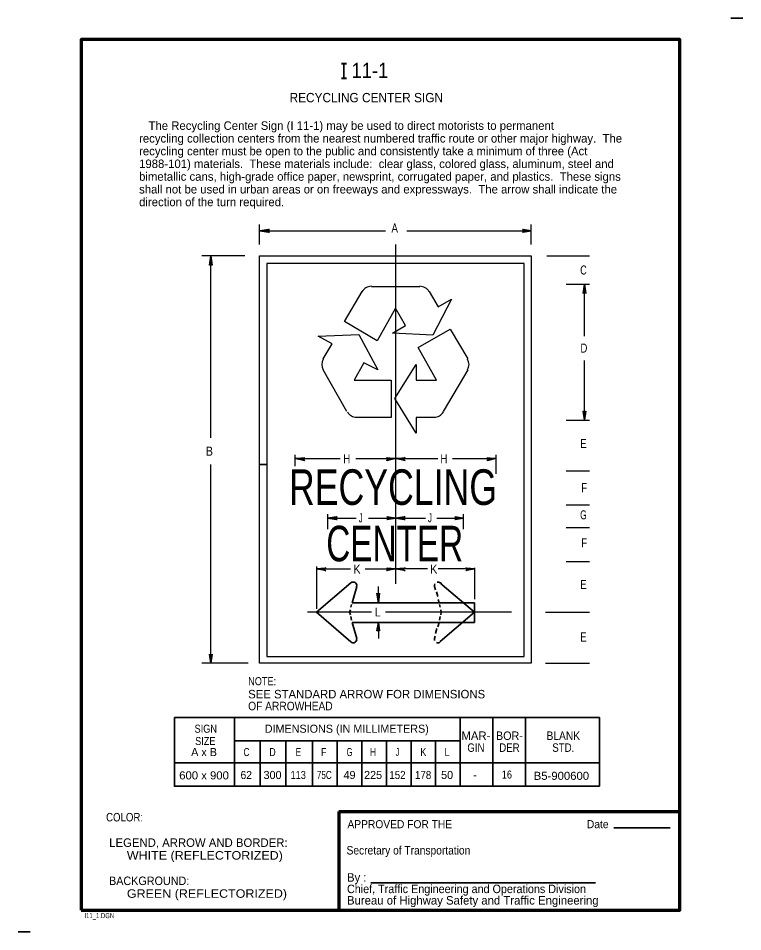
# Model space of a CAD drawing. Extents: x -17.23 to -17.016, y 260.853 to 261.123.
import ezdxf
from ezdxf.enums import TextEntityAlignment as Align

# ---------------------------------------------------------------- set-up
doc = ezdxf.new("R2010")
doc.units = 0
doc.header["$LTSCALE"] = 0.001
doc.linetypes.add('LONG_DASH_SHORT_DASH', pattern=[9.9, 6, -1.2, 1.5, -1.2])
doc.linetypes.add('MEDIUM_DASHED', pattern=[4.5, 3, -1.5])
doc.layers.add('1', color=7, linetype='Continuous', lineweight=25)
doc.layers.add('3', color=7, linetype='Continuous', lineweight=35)

msp = doc.modelspace()

# ---------------------------------------------------------------- linework, layer by layer
at = {"layer": '1', "lineweight": 35}
for p, q in [((-17.016125, 261.122625), (-17.019625, 261.122625)), ((-17.131625, 260.95625), (-17.14175, 260.947625)), ((-17.129875, 260.95525), (-17.13125, 260.950375)), ((-17.107, 260.95525), (-17.106625, 260.95425)), ((-17.10525, 260.956375), (-17.10475, 260.95575)), ((-17.106375, 260.953625), (-17.106, 260.95225)), ((-17.131375, 260.949875), (-17.131625, 260.949125)), ((-17.095125, 260.950375), (-17.13125, 260.950375)), ((-17.105875, 260.951375), (-17.105625, 260.950375)), ((-17.1055, 260.949875), (-17.10525, 260.949125)), ((-17.095125, 260.950375), (-17.095125, 260.944625)), ((-17.131625, 260.938875), (-17.14175, 260.947625)), ((-17.13175, 260.948375), (-17.132, 260.947625)), ((-17.13175, 260.946875), (-17.132, 260.947625)), ((-17.131375, 260.94525), (-17.131625, 260.946375)), ((-17.1055, 260.94525), (-17.10525, 260.946375)), ((-17.105125, 260.948375), (-17.105, 260.947625)), ((-17.105125, 260.946875), (-17.105, 260.947625)), ((-17.129875, 260.939875), (-17.13125, 260.944625)), ((-17.095125, 260.944625), (-17.13125, 260.944625)), ((-17.106, 260.943375), (-17.105625, 260.944625)), ((-17.106625, 260.941375), (-17.10625, 260.942875)), ((-17.107, 260.939875), (-17.10675, 260.940625)), ((-17.054125, 260.884125), (-17.0375, 260.884125)), ((-17.12575, 260.867875), (-17.0595, 260.867875)), ((-17.226125, 260.8535), (-17.229625, 260.8535))]:
    msp.add_line(p, q, dxfattribs=at)
at = {"layer": '1', "lineweight": 40}
for p, q in [((-17.134375, 261.10925), (-17.132875, 261.10925)), ((-17.134375, 261.105), (-17.132875, 261.105))]:
    msp.add_line(p, q, dxfattribs=at)
at = {"layer": '1'}
for p, q in [((-17.1585, 261.056), (-17.1585, 261.061875)), ((-17.1585, 261.06), (-17.121375, 261.06)), ((-17.115125, 261.06), (-17.0785, 261.06)), ((-17.0785, 261.056), (-17.0785, 261.061875)), ((-17.162875, 261.052625), (-17.1755, 261.052625)), ((-17.172875, 260.999), (-17.172875, 261.052625)), ((-17.073875, 261.052625), (-17.06125, 261.052625)), ((-17.1255, 261.043625), (-17.11125, 261.043625)), ((-17.068125, 261.04425), (-17.06125, 261.04425)), ((-17.06275, 261.029), (-17.06275, 261.04425)), ((-17.06275, 261.00425), (-17.06275, 261.02175)), ((-17.13275, 261.00675), (-17.13975, 261.019)), ((-17.097125, 261.019), (-17.104375, 261.00675)), ((-17.068125, 261.00425), (-17.06125, 261.00425)), ((-17.148125, 260.994), (-17.148125, 260.990625)), ((-17.148125, 260.992875), (-17.13475, 260.992875)), ((-17.101625, 260.992875), (-17.088875, 260.992875)), ((-17.088875, 260.994), (-17.088875, 260.988375)), ((-17.172875, 260.932625), (-17.172875, 260.991125)), ((-17.068125, 260.98925), (-17.06125, 260.98925)), ((-17.068125, 260.97925), (-17.06125, 260.97925)), ((-17.1385, 260.9765), (-17.1385, 260.972125)), ((-17.0985, 260.9765), (-17.0985, 260.972125)), ((-17.1385, 260.975375), (-17.13, 260.975375)), ((-17.10625, 260.975375), (-17.0985, 260.975375)), ((-17.068125, 260.972625), (-17.06125, 260.972625)), ((-17.068125, 260.962625), (-17.06125, 260.962625)), ((-17.14175, 260.961125), (-17.14175, 260.948625)), ((-17.14175, 260.960375), (-17.13175, 260.960375)), ((-17.127375, 260.960375), (-17.1185, 260.960375)), ((-17.109, 260.960375), (-17.1185, 260.960375)), ((-17.095125, 260.960375), (-17.105875, 260.960375)), ((-17.095125, 260.96075), (-17.095125, 260.9515)), ((-17.1235, 260.950375), (-17.1235, 260.95525)), ((-17.07425, 260.947625), (-17.06125, 260.947625)), ((-17.1235, 260.944625), (-17.1235, 260.939875)), ((-17.161875, 260.932625), (-17.1755, 260.932625)), ((-17.07425, 260.932625), (-17.06125, 260.932625))]:
    msp.add_line(p, q, dxfattribs=at)
at = {"layer": '1', "linetype": 'LONG_DASH_SHORT_DASH'}
for p, q in [((-17.1185, 261.056), (-17.1185, 260.928625)), ((-17.1255, 260.947625), (-17.144375, 260.947625)), ((-17.08425, 260.947625), (-17.121375, 260.947625))]:
    msp.add_line(p, q, dxfattribs=at)
at = {"layer": '1', "linetype": 'MEDIUM_DASHED', "lineweight": 35}
for p in [(-17.10475, 260.95575), (-17.10525, 260.939)]:
    msp.add_line(p, (-17.095125, 260.947625), dxfattribs=at)
at = {"layer": '1', "lineweight": 70}
for q in [(-17.034625, 260.888875), (-17.135125, 260.859875)]:
    msp.add_line((-17.135125, 260.888875), q, dxfattribs=at)
msp.add_lwpolyline([(-17.211125, 260.859875), (-17.034625, 260.859875), (-17.034625, 261.116375), (-17.211125, 261.116375)], close=True, dxfattribs=at)
at = {"layer": '1'}
for points in [[(-17.155875, 261.059625), (-17.156, 261.059875), (-17.1585, 261.06), (-17.155875, 261.059625), (-17.155625, 261.059625), (-17.1585, 261.06), (-17.156, 261.06025), (-17.155875, 261.060375), (-17.1585, 261.06), (-17.155625, 261.060375), (-17.155875, 261.060375)], [(-17.080875, 261.060375), (-17.080875, 261.06025), (-17.0785, 261.06), (-17.080875, 261.060375), (-17.081, 261.060375), (-17.0785, 261.06), (-17.080875, 261.059875), (-17.080875, 261.059625), (-17.0785, 261.06), (-17.081, 261.059625), (-17.080875, 261.059625)], [(-17.17325, 261.05), (-17.173125, 261.05), (-17.172875, 261.052625), (-17.17325, 261.05), (-17.17325, 261.049875), (-17.172875, 261.052625), (-17.17275, 261.05), (-17.1725, 261.05), (-17.172875, 261.052625), (-17.1725, 261.049875), (-17.1725, 261.05)], [(-17.063125, 261.04175), (-17.062875, 261.04175), (-17.06275, 261.04425), (-17.063125, 261.04175), (-17.063125, 261.0415), (-17.06275, 261.04425), (-17.0625, 261.04175), (-17.062375, 261.04175), (-17.06275, 261.04425), (-17.062375, 261.0415), (-17.062375, 261.04175)], [(-17.123875, 261.027625), (-17.1335, 261.03325), (-17.12825, 261.042125)], [(-17.1085, 261.042125), (-17.105875, 261.037625), (-17.102, 261.039875), (-17.1075, 261.02925), (-17.119375, 261.029875), (-17.1155, 261.032125), (-17.1185, 261.03725), (-17.123875, 261.027625)], [(-17.11175, 261.025625), (-17.102375, 261.031), (-17.097125, 261.02225)], [(-17.13975, 261.02225), (-17.137125, 261.02675), (-17.14125, 261.029), (-17.12925, 261.0295), (-17.123625, 261.019), (-17.12775, 261.021125), (-17.130625, 261.016), (-17.11975, 261.016)], [(-17.107125, 261.005), (-17.112375, 261.005), (-17.112375, 261.000375), (-17.118625, 261.010625), (-17.112375, 261.020625), (-17.112375, 261.016), (-17.106375, 261.016), (-17.11175, 261.025625)], [(-17.11975, 261.016), (-17.11975, 261.005), (-17.13, 261.005)], [(-17.062375, 261.00675), (-17.0625, 261.00675), (-17.06275, 261.00425), (-17.062375, 261.00675), (-17.062375, 261.006875), (-17.06275, 261.00425), (-17.062875, 261.00675), (-17.063125, 261.00675), (-17.06275, 261.00425), (-17.063125, 261.006875), (-17.063125, 261.00675)], [(-17.1455, 260.9925), (-17.1455, 260.992625), (-17.148125, 260.992875), (-17.1455, 260.9925), (-17.14525, 260.99225), (-17.148125, 260.992875), (-17.1455, 260.992875), (-17.1455, 260.993), (-17.148125, 260.992875), (-17.14525, 260.99325), (-17.1455, 260.993)], [(-17.130125, 260.992875), (-17.1185, 260.992875), (-17.106, 260.992875)], [(-17.120875, 260.993), (-17.120875, 260.992875), (-17.1185, 260.992875), (-17.120875, 260.993), (-17.121, 260.99325), (-17.1185, 260.992875), (-17.120875, 260.992625), (-17.120875, 260.9925), (-17.1185, 260.992875), (-17.121, 260.99225), (-17.120875, 260.9925)], [(-17.115875, 260.9925), (-17.116, 260.992625), (-17.1185, 260.992875), (-17.115875, 260.9925), (-17.115625, 260.99225), (-17.1185, 260.992875), (-17.116, 260.992875), (-17.115875, 260.993), (-17.1185, 260.992875), (-17.115625, 260.99325), (-17.115875, 260.993)], [(-17.091375, 260.993), (-17.09125, 260.992875), (-17.088875, 260.992875), (-17.091375, 260.993), (-17.091375, 260.99325), (-17.088875, 260.992875), (-17.09125, 260.992625), (-17.091375, 260.9925), (-17.088875, 260.992875), (-17.091375, 260.99225), (-17.091375, 260.9925)], [(-17.135875, 260.975), (-17.136, 260.97525), (-17.1385, 260.975375), (-17.135875, 260.975), (-17.135625, 260.975), (-17.1385, 260.975375), (-17.136, 260.975625), (-17.135875, 260.97575), (-17.1385, 260.975375), (-17.135625, 260.97575), (-17.135875, 260.97575)], [(-17.126375, 260.975375), (-17.1185, 260.975375), (-17.109625, 260.975375)], [(-17.120875, 260.97575), (-17.120875, 260.975625), (-17.1185, 260.975375), (-17.120875, 260.97575), (-17.121, 260.97575), (-17.1185, 260.975375), (-17.120875, 260.97525), (-17.120875, 260.975), (-17.1185, 260.975375), (-17.121, 260.975), (-17.120875, 260.975)], [(-17.115875, 260.975), (-17.116, 260.97525), (-17.1185, 260.975375), (-17.115875, 260.975), (-17.115625, 260.975), (-17.1185, 260.975375), (-17.116, 260.975625), (-17.115875, 260.97575), (-17.1185, 260.975375), (-17.115625, 260.97575), (-17.115875, 260.97575)], [(-17.100875, 260.97575), (-17.100875, 260.975625), (-17.0985, 260.975375), (-17.100875, 260.97575), (-17.101, 260.97575), (-17.0985, 260.975375), (-17.100875, 260.97525), (-17.100875, 260.975), (-17.0985, 260.975375), (-17.101, 260.975), (-17.100875, 260.975)], [(-17.13925, 260.96), (-17.139375, 260.96025), (-17.14175, 260.960375), (-17.13925, 260.96), (-17.139, 260.959875), (-17.14175, 260.960375), (-17.139375, 260.960375), (-17.13925, 260.960625), (-17.14175, 260.960375), (-17.139, 260.96075), (-17.13925, 260.960625)], [(-17.120875, 260.960625), (-17.120875, 260.960375), (-17.1185, 260.960375), (-17.120875, 260.960625), (-17.121, 260.96075), (-17.1185, 260.960375), (-17.120875, 260.96025), (-17.120875, 260.96), (-17.1185, 260.960375), (-17.121, 260.959875), (-17.120875, 260.96)], [(-17.115875, 260.96), (-17.116, 260.96025), (-17.1185, 260.960375), (-17.115875, 260.96), (-17.115625, 260.959875), (-17.1185, 260.960375), (-17.116, 260.960375), (-17.115875, 260.960625), (-17.1185, 260.960375), (-17.115625, 260.96075), (-17.115875, 260.960625)], [(-17.0975, 260.960625), (-17.0975, 260.960375), (-17.095125, 260.960375), (-17.0975, 260.960625), (-17.09775, 260.96075), (-17.095125, 260.960375), (-17.0975, 260.96025), (-17.0975, 260.96), (-17.095125, 260.960375), (-17.09775, 260.959875), (-17.0975, 260.96)], [(-17.123125, 260.953), (-17.12325, 260.953), (-17.1235, 260.950375), (-17.123125, 260.953), (-17.123125, 260.95325), (-17.1235, 260.950375), (-17.123625, 260.953), (-17.123875, 260.953), (-17.1235, 260.950375), (-17.124, 260.95325), (-17.123875, 260.953)], [(-17.123875, 260.942125), (-17.123625, 260.94225), (-17.1235, 260.944625), (-17.123875, 260.942125), (-17.124, 260.942125), (-17.1235, 260.944625), (-17.1235, 260.94225), (-17.12325, 260.942125), (-17.1235, 260.944625), (-17.123125, 260.942125), (-17.12325, 260.942125)], [(-17.1725, 260.935), (-17.17275, 260.935), (-17.172875, 260.932625), (-17.1725, 260.935), (-17.1725, 260.93525), (-17.172875, 260.932625), (-17.172875, 260.935), (-17.173125, 260.935), (-17.172875, 260.932625), (-17.17325, 260.93525), (-17.173125, 260.935)]]:
    msp.add_lwpolyline(points, dxfattribs=at)
for points in [[(-17.1585, 260.991125), (-17.1585, 261.052625), (-17.0785, 261.052625), (-17.0785, 260.932625), (-17.1585, 260.932625)], [(-17.1585, 260.991125), (-17.156375, 260.991125), (-17.156375, 260.934625), (-17.0805, 260.934625), (-17.0805, 261.050375), (-17.156375, 261.050375), (-17.156375, 260.991125)]]:
    msp.add_lwpolyline(points, close=True, dxfattribs=at)
for centre, start, end in [((-17.125557, 261.040455), 90, 149.99887), ((-17.111287, 261.040455), 29.99896, 90), ((-17.137002, 261.02063), 149.99896, 210), ((-17.099991, 261.020629), 330, 29.99887), ((-17.129868, 261.008273), 210, 269.99887), ((-17.107126, 261.008271), 269.99896, 330)]:
    msp.add_arc(centre, 0.003204, start, end, dxfattribs=at)
at = {"layer": '1', "lineweight": 35}
for centre, start, end in [((-17.130922, 260.955493), 345.06766, 130.69576), ((-17.105922, 260.955493), 149.73225, 194.93234), ((-17.105922, 260.955493), 49.30424, 102.74836), ((-17.130922, 260.93966), 229.30424, 14.93234), ((-17.105922, 260.93966), 165.06766, 197.21544), ((-17.105922, 260.93966), 243.42871, 310.69576)]:
    msp.add_arc(centre, 0.001042, start, end, dxfattribs=at)
at = {"layer": '3'}
for p, q in [((-17.183625, 260.916625), (-17.058375, 260.916625)), ((-17.165875, 260.916625), (-17.165875, 260.896375)), ((-17.099375, 260.916625), (-17.099375, 260.896375)), ((-17.08975, 260.916625), (-17.08975, 260.896375)), ((-17.080125, 260.916625), (-17.080125, 260.896375)), ((-17.058375, 260.916625), (-17.058375, 260.896375)), ((-17.099375, 260.90975), (-17.165875, 260.90975)), ((-17.158375, 260.90975), (-17.158375, 260.896375)), ((-17.15075, 260.90975), (-17.15075, 260.896375)), ((-17.142875, 260.90975), (-17.142875, 260.896375)), ((-17.135625, 260.90975), (-17.135625, 260.896375)), ((-17.128375, 260.90975), (-17.128375, 260.896375)), ((-17.121125, 260.90975), (-17.121125, 260.896375)), ((-17.113875, 260.90975), (-17.113875, 260.896375)), ((-17.106625, 260.90975), (-17.106625, 260.896375)), ((-17.183625, 260.90325), (-17.058375, 260.90325))]:
    msp.add_line(p, q, dxfattribs=at)
msp.add_lwpolyline([(-17.183625, 260.916625), (-17.183625, 260.896375), (-17.058375, 260.896375)], dxfattribs=at)

# ---------------------------------------------------------------- texts
at = {"layer": '1'}
for s, height, width, p in [('I 11-1', 0.0045, 0.9, (-17.1275, 261.105)), ('RECYCLING CENTER SIGN', 0.00275, 0.95, (-17.127063, 261.097875)), ('A', 0.002663, 0.8, (-17.118688, 261.0595)), ('C', 0.002663, 0.75, (-17.063063, 261.047125)), ('D', 0.002663, 0.8, (-17.062938, 261.024125)), ('E', 0.002663, 0.8, (-17.063063, 260.996)), ('B', 0.002663, 0.9, (-17.173313, 260.99375)), ('H', 0.002663, 0.8, (-17.132812, 260.9915)), ('H', 0.002663, 0.8, (-17.104188, 260.9915)), ('RECYCLING', 0.01048, 0.75, (-17.119187, 260.97925)), ('F', 0.002663, 0.8, (-17.062875, 260.983)), ('J', 0.002663, 0.65, (-17.128688, 260.974125)), ('J', 0.002663, 0.65, (-17.108313, 260.974125)), ('G', 0.002663, 0.7, (-17.063063, 260.975)), ('CENTER', 0.01048, 0.7, (-17.118688, 260.962625)), ('F', 0.002663, 0.8, (-17.062875, 260.96675)), ('K', 0.002663, 0.9, (-17.129812, 260.959)), ('K', 0.002663, 0.9, (-17.107188, 260.959)), ('E', 0.002663, 0.8, (-17.063063, 260.9545)), ('L', 0.002625, 0.85, (-17.123687, 260.946375)), ('E', 0.002663, 0.8, (-17.063063, 260.939)), ('APPROVED FOR THE', 0.002375, 0.95, (-17.117188, 260.884)), ('Date ', 0.002375, 0.95, (-17.058438, 260.884))]:
    msp.add_text(s, height=height, dxfattribs=dict(at, width=width)).set_placement(p, align=Align.CENTER)
for s, height, width, p in [('NOTE:', 0.002375, 0.85, (-17.161875, 260.926125)), ('OF ARROWHEAD', 0.0025, 0.9, (-17.161875, 260.91875)), ('COLOR:', 0.0025, 0.85, (-17.20375, 260.886)), ('      WHITE (REFLECTORIZED)', 0.0025, 1.1, (-17.20375, 260.87475)), ('Secretary of Transportation', 0.0025, 0.9, (-17.132875, 260.87625)), (' BACKGROUND:', 0.0025, 0.95, (-17.20375, 260.86725)), ('      GREEN (REFLECTORIZED)', 0.0025, 1.1, (-17.20375, 260.8635)), ('Chief, Traffic Engineering and Operations Division', 0.0025, 0.95, (-17.13275, 260.864875)), ('I11_1.DGN', 0.0015, 0.7, (-17.210125, 260.8575))]:
    msp.add_text(s, height=height, dxfattribs=dict(at, width=width)).set_placement(p)
for s, p in [('SEE STANDARD ARROW FOR DIMENSIONS', (-17.161875, 260.92225)), (' LEGEND, ARROW AND BORDER:', (-17.20375, 260.8785)), ('By :', (-17.13275, 260.86825)), ('Bureau of Highway Safety and Traffic Engineering', (-17.13275, 260.8615))]:
    msp.add_text(s, height=0.0025, dxfattribs=at).set_placement(p)
at = {"layer": '3'}
for s, p in [('     The Recycling Center Sign (I 11-1) may be used to direct motorists to permanent', (-17.195875, 261.08975)), ('  recycling collection centers from the nearest numbered traffic route or other major highway.  The', (-17.195875, 261.086)), ('  recycling center must be open to the public and consistently take a minimum of three (Act ', (-17.195875, 261.08225)), ('  1988-101) materials.  These materials include:  clear glass, colored glass, aluminum, steel and', (-17.195875, 261.0785)), ('  bimetallic cans, high-grade office paper, newsprint, corrugated paper, and plastics.  These signs', (-17.195875, 261.07475)), ('  shall not be used in urban areas or on freeways and expressways.  The arrow shall indicate the', (-17.195875, 261.071)), ('  direction of the turn required. ', (-17.195875, 261.06725))]:
    msp.add_text(s, height=0.0025, dxfattribs=at).set_placement(p)
for s, height, width, p in [('SIGN', 0.002375, 0.85, (-17.174375, 260.912125)), ('BOR-', 0.0025, 0.95, (-17.084875, 260.91)), ('BLANK', 0.0025, 0.9, (-17.069, 260.91)), ('SIZE', 0.002375, 0.85, (-17.1745, 260.9085)), ('GIN', 0.0025, 0.85, (-17.09475, 260.9065)), ('DER', 0.0025, 0.85, (-17.084875, 260.9065)), ('STD.', 0.0025, 0.85, (-17.069, 260.9065)), ('C', 0.002375, 0.75, (-17.162375, 260.90525)), ('D', 0.002375, 0.8, (-17.154688, 260.90525)), ('E', 0.002375, 0.75, (-17.147063, 260.90525)), ('F', 0.002375, 0.8, (-17.139625, 260.90525)), ('G', 0.002375, 0.7, (-17.132, 260.90525)), ('H', 0.002375, 0.8, (-17.125063, 260.90525)), ('J', 0.002375, 0.65, (-17.117875, 260.90525)), ('K', 0.002375, 0.85, (-17.11025, 260.90525)), ('L', 0.002375, 0.85, (-17.10325, 260.90525)), ('600 x 900', 0.002375, 1.05, (-17.174875, 260.898375)), ('62', 0.002375, 0.95, (-17.162437, 260.8985)), ('113', 0.002375, 0.85, (-17.147125, 260.8985)), ('75C', 0.002375, 0.75, (-17.139437, 260.8985)), ('152', 0.002375, 0.9, (-17.117875, 260.8985)), ('178', 0.002375, 0.9, (-17.110312, 260.8985)), ('16', 0.002375, 0.85, (-17.085625, 260.898625)), ('B5-900600', 0.002375, 1.05, (-17.069562, 260.89825))]:
    msp.add_text(s, height=height, dxfattribs=dict(at, width=width)).set_placement(p, align=Align.CENTER)
for s, height, p in [('DIMENSIONS (IN MILLIMETERS)', 0.002375, (-17.132812, 260.912125)), ('MAR-', 0.0025, (-17.09475, 260.91)), ('A x B', 0.002375, (-17.174875, 260.90525)), ('300', 0.002375, (-17.154688, 260.8985)), ('49', 0.002375, (-17.132, 260.8985)), ('225', 0.002375, (-17.125063, 260.8985)), ('50', 0.002375, (-17.10325, 260.8985)), ('-', 0.002375, (-17.095, 260.8985))]:
    msp.add_text(s, height=height, dxfattribs=at).set_placement(p, align=Align.CENTER)

doc.saveas('drawing.dxf')
